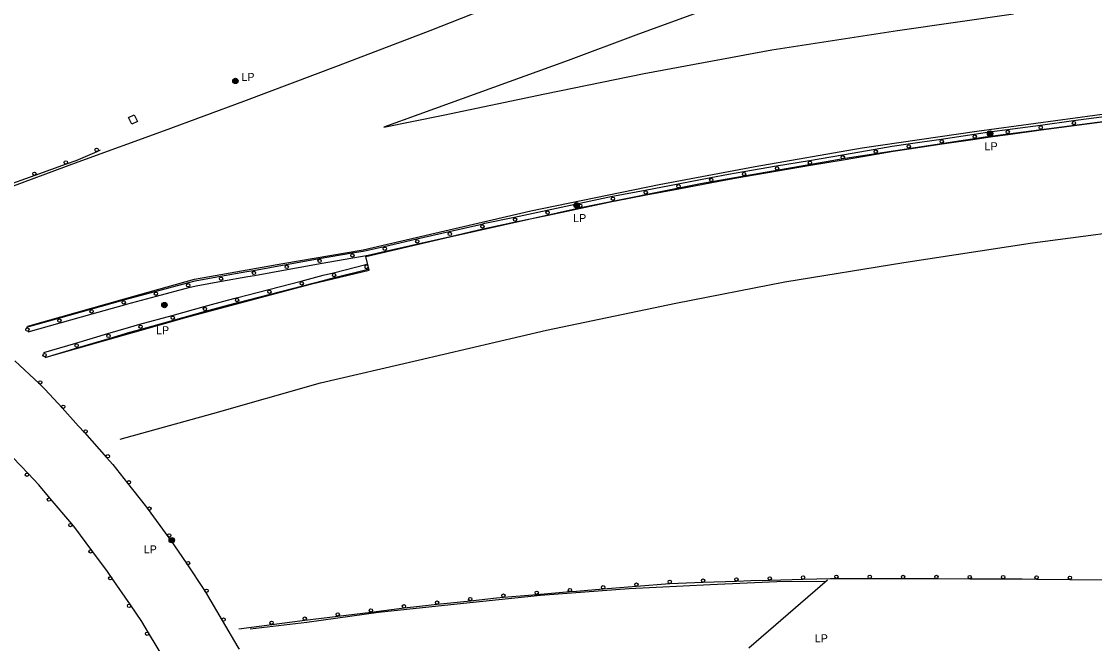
# Model space of a CAD drawing. Extents: x 2402803 to 2427059, y 6985292 to 6997652.
# Drawn here: x 2411121 to 2411764, y 6991642 to 6992015 of the extents above; entities that cross this region are included whole.
import ezdxf

# ---------------------------------------------------------------- set-up
doc = ezdxf.new("R2010")
doc.units = 0
for name, color, linetype in [('p_road - paved curb', 7, 'Continuous'), ('p_road bridge end', 7, 'Continuous'), ('p_road conc barrier', 7, 'Continuous'), ('p_road guard rails', 7, 'Continuous'), ('p_utility manhole', 7, 'Continuous')]:
    doc.layers.add(name, color=color, linetype=linetype)

msp = doc.modelspace()

# ---------------------------------------------------------------- linework, layer by layer
at = {"layer": 'p_road - paved curb'}
for points in [[(2411107.33, 6991913.27), (2411154.95, 6991930.9), (2411206.69, 6991949.66), (2411254.19, 6991967.25), (2411311.09, 6991988.6), (2411365.88, 6992009.61), (2411415.79, 6992029.31), (2411462.98, 6992047.29), (2411522.68, 6992069.89), (2411577.83, 6992090.57), (2411628.55, 6992107.53), (2411687.94, 6992126.55), (2411753.96, 6992146.21), (2411823.39, 6992164.69), (2411887.31, 6992180.13), (2411962.42, 6992196.28), (2412027.75, 6992208.99), (2412098.13, 6992220.7), (2412152.3, 6992229.59), (2412184.05, 6992234.29)], [(2411552.35, 6992029.86), (2411489.19, 6992006.82), (2411448.61, 6991991.51), (2411359.21, 6991959.2), (2411338.15, 6991951.56), (2411373.82, 6991958.72), (2411434.8, 6991971.67), (2411494.29, 6991983.73), (2411570.87, 6991997.94), (2411646.13, 6992009.54), (2411715.6, 6992019.45)], [(2411124.72, 6991832.32), (2411191.91, 6991851.4), (2411224.61, 6991860.58), (2411277.54, 6991869.86), (2411325.84, 6991878.14), (2411426.37, 6991901.41), (2411503.26, 6991917.26), (2411560.71, 6991928.04), (2411625.03, 6991939.17), (2411693.75, 6991949.3), (2411787.97, 6991962), (2411871.05, 6991970.96), (2411944.54, 6991977.06), (2412037.63, 6991983.69), (2412123.21, 6991987.02), (2412234.99, 6991988.48), (2412320.38, 6991987.98)], [(2411139.21, 6991814.81), (2411220.09, 6991837.73), (2411295.01, 6991857.74), (2411329.29, 6991866), (2411327.29, 6991874.1), (2411377.82, 6991885.88), (2411457.26, 6991903.64), (2411527.97, 6991917.78), (2411614.67, 6991933.09), (2411698.69, 6991945.86), (2411798.18, 6991958.82), (2411874.49, 6991966.79), (2411952.86, 6991973.27), (2412059.62, 6991980.22), (2412152.49, 6991983.28), (2412320.8, 6991983.74)], [(2411180.03, 6991764.55), (2411235.65, 6991780.07), (2411300.12, 6991798.32), (2411358.85, 6991811.99), (2411435.65, 6991830.04), (2411513.27, 6991846.24), (2411578.55, 6991858.97), (2411650.01, 6991870.54), (2411727.01, 6991882.37), (2411805.96, 6991892.73)], [(2411258.06, 6991651), (2411291.97, 6991654.98), (2411334.89, 6991660.89), (2411382.12, 6991665.94), (2411432.08, 6991671.19), (2411485.24, 6991675.11), (2411533.76, 6991677.61), (2411573.74, 6991679.42), (2411603.08, 6991679.58)]]:
    msp.add_lwpolyline(points, dxfattribs=at)
at = {"layer": 'p_road bridge end'}
msp.add_lwpolyline([(2411185.19, 6991957.43), (2411188.45, 6991959.03), (2411190.43, 6991955.05), (2411187.17, 6991953.45)], close=True, dxfattribs=at)
msp.add_lwpolyline([(2411557.07, 6991639.65), (2411604.19, 6991680.37)], dxfattribs=at)
at = {"layer": 'p_road conc barrier'}
for p, q in [((2411751.68, 6991955.58), (2411771.5, 6991958.24)), ((2411712.04, 6991950.25), (2411731.86, 6991952.91)), ((2411712.44, 6991947.27), (2411732.26, 6991949.94)), ((2411731.86, 6991952.91), (2411751.68, 6991955.58)), ((2411732.26, 6991949.94), (2411752.08, 6991952.6)), ((2411752.08, 6991952.6), (2411771.9, 6991955.27)), ((2411652.63, 6991941.6), (2411672.42, 6991944.52)), ((2411672.42, 6991944.52), (2411692.2, 6991947.44)), ((2411672.85, 6991941.55), (2411692.64, 6991944.47)), ((2411613.1, 6991935.09), (2411632.82, 6991938.44)), ((2411653.07, 6991938.63), (2411672.85, 6991941.55)), ((2411573.67, 6991928.37), (2411593.38, 6991931.73)), ((2411593.38, 6991931.73), (2411613.1, 6991935.09)), ((2411593.89, 6991928.77), (2411613.6, 6991932.13)), ((2411613.6, 6991932.13), (2411633.32, 6991935.49)), ((2411553.95, 6991925.02), (2411573.67, 6991928.37)), ((2411554.45, 6991922.06), (2411574.17, 6991925.42)), ((2411574.17, 6991925.42), (2411593.89, 6991928.77)), ((2411494.92, 6991913.95), (2411514.57, 6991917.7)), ((2411514.57, 6991917.7), (2411534.21, 6991921.44)), ((2411515.13, 6991914.75), (2411534.78, 6991918.5)), ((2411495.48, 6991911.01), (2411515.13, 6991914.75)), ((2411436.09, 6991901.88), (2411455.65, 6991906.03)), ((2411455.65, 6991906.03), (2411475.22, 6991910.17)), ((2411456.28, 6991903.09), (2411475.84, 6991907.23)), ((2411416.52, 6991897.74), (2411436.09, 6991901.88)), ((2411417.14, 6991894.81), (2411436.71, 6991898.95)), ((2411436.71, 6991898.95), (2411456.28, 6991903.09)), ((2411377.42, 6991889.1), (2411396.91, 6991893.56)), ((2411357.93, 6991884.65), (2411377.42, 6991889.1)), ((2411358.59, 6991881.72), (2411378.09, 6991886.18)), ((2411378.09, 6991886.18), (2411397.58, 6991890.63)), ((2411338.43, 6991880.19), (2411357.93, 6991884.65)), ((2411339.1, 6991877.26), (2411358.59, 6991881.72)), ((2411299.41, 6991872.93), (2411319.13, 6991876.23)), ((2411299.91, 6991869.97), (2411319.62, 6991873.27)), ((2411260.02, 6991865.76), (2411279.69, 6991869.35)), ((2411260.56, 6991862.81), (2411280.23, 6991866.4)), ((2411307.96, 6991864.4), (2411327.34, 6991869.32)), ((2411308.69, 6991861.49), (2411328.08, 6991866.41)), ((2411327.34, 6991869.32), (2411328.08, 6991869.51)), ((2411328.08, 6991866.41), (2411328.82, 6991866.6)), ((2411201.15, 6991853.2), (2411220.48, 6991858.35)), ((2411201.93, 6991850.31), (2411221.25, 6991855.45)), ((2411249.84, 6991849.43), (2411269.21, 6991854.43)), ((2411269.21, 6991854.43), (2411288.57, 6991859.42)), ((2411269.96, 6991851.52), (2411289.32, 6991856.52)), ((2411162.54, 6991842.6), (2411181.79, 6991848.03)), ((2411250.59, 6991846.52), (2411269.96, 6991851.52)), ((2411143.29, 6991837.18), (2411162.54, 6991842.6)), ((2411163.36, 6991839.72), (2411182.61, 6991845.14)), ((2411211.22, 6991838.83), (2411230.49, 6991844.17)), ((2411212.02, 6991835.94), (2411231.29, 6991841.28)), ((2411124.04, 6991831.76), (2411143.29, 6991837.18)), ((2411124.86, 6991828.87), (2411144.11, 6991834.29)), ((2411144.11, 6991834.29), (2411163.36, 6991839.72)), ((2411191.94, 6991833.5), (2411211.22, 6991838.83)), ((2411192.74, 6991830.61), (2411212.02, 6991835.94)), ((2411153.51, 6991822.2), (2411172.68, 6991827.91)), ((2411134.34, 6991816.5), (2411153.51, 6991822.2)), ((2411154.37, 6991819.33), (2411173.54, 6991825.03)), ((2411135.2, 6991813.63), (2411154.37, 6991819.33))]:
    msp.add_line(p, q, dxfattribs=at)
for points in [[(2411692.2, 6991947.44), (2411702.75, 6991949), (2411712.04, 6991950.25)], [(2411692.64, 6991944.47), (2411703.17, 6991946.03), (2411712.44, 6991947.27)], [(2411632.82, 6991938.44), (2411643.03, 6991940.18), (2411652.63, 6991941.6)], [(2411633.32, 6991935.49), (2411643.5, 6991937.22), (2411653.07, 6991938.63)], [(2411534.21, 6991921.44), (2411544.79, 6991923.46), (2411553.95, 6991925.02)], [(2411534.78, 6991918.5), (2411545.32, 6991920.5), (2411554.45, 6991922.06)], [(2411475.22, 6991910.17), (2411476.56, 6991910.45), (2411494.92, 6991913.95)], [(2411475.84, 6991907.23), (2411477.15, 6991907.51), (2411495.48, 6991911.01)], [(2411396.91, 6991893.56), (2411398.83, 6991894), (2411416.52, 6991897.74)], [(2411397.58, 6991890.63), (2411399.48, 6991891.07), (2411417.14, 6991894.81)], [(2411319.13, 6991876.23), (2411325.88, 6991877.36), (2411325.88, 6991877.32), (2411338.43, 6991880.19)], [(2411279.69, 6991869.35), (2411298.44, 6991872.77), (2411299.41, 6991872.93)], [(2411319.62, 6991873.27), (2411328.88, 6991874.82), (2411328.88, 6991874.93), (2411339.1, 6991877.26)], [(2411280.23, 6991866.4), (2411298.96, 6991869.81), (2411299.91, 6991869.97)], [(2411220.48, 6991858.35), (2411225, 6991859.56), (2411240.34, 6991862.27)], [(2411240.34, 6991862.27), (2411256.14, 6991865.06), (2411260.02, 6991865.76)], [(2411240.86, 6991859.31), (2411256.67, 6991862.1), (2411260.56, 6991862.81)], [(2411288.57, 6991859.42), (2411301.87, 6991862.86), (2411307.96, 6991864.4)], [(2411289.32, 6991856.52), (2411302.61, 6991859.95), (2411308.69, 6991861.49)], [(2411181.79, 6991848.03), (2411183.08, 6991848.39), (2411201.15, 6991853.2)], [(2411221.25, 6991855.45), (2411225.65, 6991856.63), (2411240.86, 6991859.31)], [(2411182.61, 6991845.14), (2411183.87, 6991845.5), (2411201.93, 6991850.31)], [(2411230.49, 6991844.17), (2411244.43, 6991848.03), (2411249.84, 6991849.43)], [(2411231.29, 6991841.28), (2411245.21, 6991845.13), (2411250.59, 6991846.52)], [(2411172.68, 6991827.91), (2411185.08, 6991831.59), (2411191.94, 6991833.5)], [(2411173.54, 6991825.03), (2411185.9, 6991828.71), (2411192.74, 6991830.61)]]:
    msp.add_lwpolyline(points, dxfattribs=at)
for centre in [(2411712.24, 6991948.76), (2411732.06, 6991951.42), (2411751.88, 6991954.09), (2411672.63, 6991943.04), (2411692.42, 6991945.96), (2411633.07, 6991936.97), (2411652.85, 6991940.12), (2411593.63, 6991930.25), (2411613.35, 6991933.61), (2411554.2, 6991923.54), (2411573.92, 6991926.9), (2411534.49, 6991919.97), (2411495.2, 6991912.48), (2411514.85, 6991916.22), (2411455.96, 6991904.56), (2411475.53, 6991908.7), (2411436.4, 6991900.42), (2411397.25, 6991892.1), (2411416.83, 6991896.27), (2411377.75, 6991887.64), (2411338.77, 6991878.73), (2411358.26, 6991883.18), (2411299.66, 6991871.45), (2411319.37, 6991874.75), (2411279.96, 6991867.88), (2411240.6, 6991860.79), (2411260.29, 6991864.29), (2411308.33, 6991862.95), (2411220.87, 6991856.9), (2411269.58, 6991852.97), (2411288.95, 6991857.97), (2411182.2, 6991846.58), (2411201.54, 6991851.75), (2411250.22, 6991847.98), (2411162.95, 6991841.16), (2411230.89, 6991842.73), (2411143.7, 6991835.74), (2411211.62, 6991837.39), (2411124.45, 6991830.31), (2411173.11, 6991826.47), (2411192.34, 6991832.05), (2411153.94, 6991820.77), (2411134.77, 6991815.06)]:
    msp.add_circle(centre, 1, dxfattribs=at)
msp.add_arc((2411327.71, 6991867.87), 1, 54.78199, 333.69135, dxfattribs=at)
at = {"layer": 'p_road guard rails'}
for p, q in [((2411166.34, 6991937.11), (2411168.29, 6991937.95)), ((2411129.05, 6991922.76), (2411147.86, 6991929.55)), ((2411110.24, 6991915.96), (2411129.05, 6991922.76)), ((2411116.96, 6991811.64), (2411131.49, 6991797.92)), ((2411158.65, 6991768.65), (2411171.97, 6991753.75)), ((2411124.92, 6991744.05), (2411111.2, 6991758.54)), ((2411151.04, 6991713.83), (2411138.18, 6991729.13)), ((2411196.83, 6991722.44), (2411208.73, 6991706.38)), ((2411186.27, 6991665.33), (2411175, 6991681.83)), ((2411529.59, 6991678.88), (2411549.57, 6991679.61)), ((2411569.55, 6991680.23), (2411589.52, 6991680.75)), ((2411609.5, 6991681.18), (2411629.5, 6991681.14)), ((2411629.5, 6991681.14), (2411649.5, 6991681.1)), ((2411649.5, 6991681.1), (2411669.49, 6991681.05)), ((2411669.49, 6991681.05), (2411689.49, 6991681.01)), ((2411689.49, 6991681.01), (2411709.49, 6991680.96)), ((2411729.49, 6991680.84), (2411749.49, 6991680.61)), ((2411749.49, 6991680.61), (2411769.48, 6991680.39)), ((2411231.08, 6991673.29), (2411241.25, 6991656.07)), ((2411429.9, 6991671.57), (2411449.82, 6991673.26)), ((2411469.75, 6991674.9), (2411489.68, 6991676.53)), ((2411509.61, 6991678.15), (2411529.59, 6991678.88)), ((2411370.21, 6991665.73), (2411390.09, 6991667.86)), ((2411409.98, 6991669.89), (2411429.9, 6991671.57)), ((2411310.68, 6991658.65), (2411330.52, 6991661.06)), ((2411330.52, 6991661.06), (2411350.35, 6991663.48)), ((2411271.02, 6991653.61), (2411290.85, 6991656.15)), ((2411207.42, 6991631.44), (2411197.14, 6991648.58)), ((2411251.19, 6991651.08), (2411271.02, 6991653.61))]:
    msp.add_line(p, q, dxfattribs=at)
for points in [[(2411147.86, 6991929.55), (2411153.8, 6991931.7), (2411166.34, 6991937.11)], [(2411131.49, 6991797.92), (2411135.23, 6991794.39), (2411145.23, 6991783.44)], [(2411145.23, 6991783.44), (2411155.18, 6991772.53), (2411158.65, 6991768.65)], [(2411171.97, 6991753.75), (2411175.8, 6991749.46), (2411184.57, 6991738.24)], [(2411138.18, 6991729.13), (2411131.26, 6991737.36), (2411124.92, 6991744.05)], [(2411184.57, 6991738.24), (2411195.06, 6991724.83), (2411196.83, 6991722.44)], [(2411163.16, 6991697.94), (2411152.83, 6991711.71), (2411151.04, 6991713.83)], [(2411208.73, 6991706.38), (2411210.16, 6991704.44), (2411219.97, 6991689.87)], [(2411175, 6991681.83), (2411172.53, 6991685.44), (2411163.16, 6991697.94)], [(2411219.97, 6991689.87), (2411230.65, 6991674.02), (2411231.08, 6991673.29)], [(2411549.57, 6991679.61), (2411558.28, 6991679.93), (2411569.55, 6991680.23)], [(2411589.52, 6991680.75), (2411606.02, 6991681.19), (2411609.5, 6991681.18)], [(2411709.49, 6991680.96), (2411720.8, 6991680.94), (2411729.49, 6991680.84)], [(2411449.82, 6991673.26), (2411453.77, 6991673.59), (2411469.75, 6991674.9)], [(2411489.68, 6991676.53), (2411509.35, 6991678.14), (2411509.61, 6991678.15)], [(2411390.09, 6991667.86), (2411405.78, 6991669.53), (2411409.98, 6991669.89)], [(2411197.14, 6991648.58), (2411193.05, 6991655.41), (2411186.27, 6991665.33)], [(2411350.35, 6991663.48), (2411359.6, 6991664.6), (2411370.21, 6991665.73)], [(2411241.25, 6991656.07), (2411250.73, 6991640), (2411251.35, 6991638.81)], [(2411290.85, 6991656.15), (2411305.88, 6991658.07), (2411310.68, 6991658.65)]]:
    msp.add_lwpolyline(points, dxfattribs=at)
for centre in [(2411165.95, 6991938.03), (2411147.52, 6991930.49), (2411128.71, 6991923.7), (2411132.18, 6991798.64), (2411145.97, 6991784.11), (2411159.39, 6991769.32), (2411172.71, 6991754.41), (2411124.2, 6991743.36), (2411185.36, 6991738.86), (2411137.42, 6991728.48), (2411197.63, 6991723.04), (2411150.28, 6991713.19), (2411209.53, 6991706.97), (2411162.36, 6991697.34), (2411220.8, 6991690.43), (2411174.17, 6991681.27), (2411509.57, 6991679.15), (2411529.56, 6991679.88), (2411549.54, 6991680.61), (2411569.52, 6991681.23), (2411589.49, 6991681.75), (2411609.5, 6991682.18), (2411629.5, 6991682.14), (2411649.5, 6991682.1), (2411669.5, 6991682.05), (2411689.5, 6991682.01), (2411709.5, 6991681.96), (2411729.5, 6991681.84), (2411749.5, 6991681.61), (2411231.94, 6991673.79), (2411429.82, 6991672.57), (2411449.74, 6991674.25), (2411469.67, 6991675.89), (2411489.6, 6991677.53), (2411370.11, 6991666.73), (2411389.99, 6991668.85), (2411409.9, 6991670.88), (2411185.44, 6991664.77), (2411310.56, 6991659.65), (2411330.4, 6991662.06), (2411350.23, 6991664.47), (2411242.11, 6991656.57), (2411270.89, 6991654.61), (2411290.72, 6991657.14), (2411196.29, 6991648.07)]:
    msp.add_circle(centre, 1, dxfattribs=at)
at = {"layer": 'p_utility manhole'}
for centre, radius in [((2411249.21, 6991979.33), 1.6), ((2411249.21, 6991979.33), 1.3), ((2411249.21, 6991979.33), 1), ((2411249.21, 6991979.33), 0.539), ((2411249.21, 6991979.33), 0.192), ((2411701.62, 6991947.8), 1.6), ((2411701.62, 6991947.8), 1.3), ((2411701.62, 6991947.8), 1), ((2411701.62, 6991947.8), 0.539), ((2411701.62, 6991947.8), 0.192), ((2411453.77, 6991904.81), 1.6), ((2411453.77, 6991904.81), 1.3), ((2411453.77, 6991904.81), 1), ((2411453.77, 6991904.81), 0.539), ((2411453.77, 6991904.81), 0.192), ((2411206.62, 6991844.98), 1.6), ((2411206.62, 6991844.98), 1.3), ((2411206.62, 6991844.98), 1), ((2411206.62, 6991844.98), 0.539), ((2411206.62, 6991844.98), 0.192), ((2411211.05, 6991704.14), 1.6), ((2411211.05, 6991704.14), 1.3), ((2411211.05, 6991704.14), 1), ((2411211.05, 6991704.14), 0.539), ((2411211.05, 6991704.14), 0.192)]:
    msp.add_circle(centre, radius, dxfattribs=at)

# ---------------------------------------------------------------- texts
for p in [(2411249.21, 6991979.33), (2411694.76, 6991937.79), (2411448.1, 6991894.72), (2411198.02, 6991827.52), (2411190.65, 6991696.22), (2411592.98, 6991642.92)]:
    msp.add_text('  LP', height=4.8, dxfattribs=at).set_placement(p)

doc.saveas('drawing.dxf')
